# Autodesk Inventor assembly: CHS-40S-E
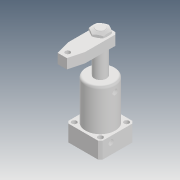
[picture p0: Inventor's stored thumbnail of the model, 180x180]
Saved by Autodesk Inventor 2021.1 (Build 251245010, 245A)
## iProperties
Created: 2019-04
Part Number: CHS-40S-E
Description: STEP AP203
Document SubType Name: Assembly
Designer: user
Title: chs-40s-e_asm.STEP
Revision Number: ÈÎºÎ
Sending System: SolidWorks 2017
Preprocessor: SwSTEP 2.0
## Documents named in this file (5)
- D:\Vault_2016\Projekty\Clamptek\Hydraulic\CHS\CHS-40\Inventor\CHS-40S-E\CHS-40S-E.iam
- D:\Vault_2016\Projekty\Clamptek\Hydraulic\CHS\CHS-40\Inventor\CHS-40S-E\CHS-40-03-E_1.ipt
- D:\Vault_2016\Projekty\Clamptek\Hydraulic\CHS\CHS-40\Inventor\CHS-40S-E\CHS-40S-02-E_1.ipt
- D:\Vault_2016\Projekty\Clamptek\Hydraulic\CHS\CHS-40\Inventor\CHS-40S-E\CHS-40S-01_1.ipt
- D:\Vault_2016\Projekty\Clamptek\Hydraulic\CHS\CHS-40\Inventor\CHS-40S-E\M18_1.ipt
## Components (4 placed, 4 different names)
1. CHS-40-03-E_1_1
2. CHS-40S-02-E_1_2
3. CHS-40S-01_1_3
4. M18_1_4
